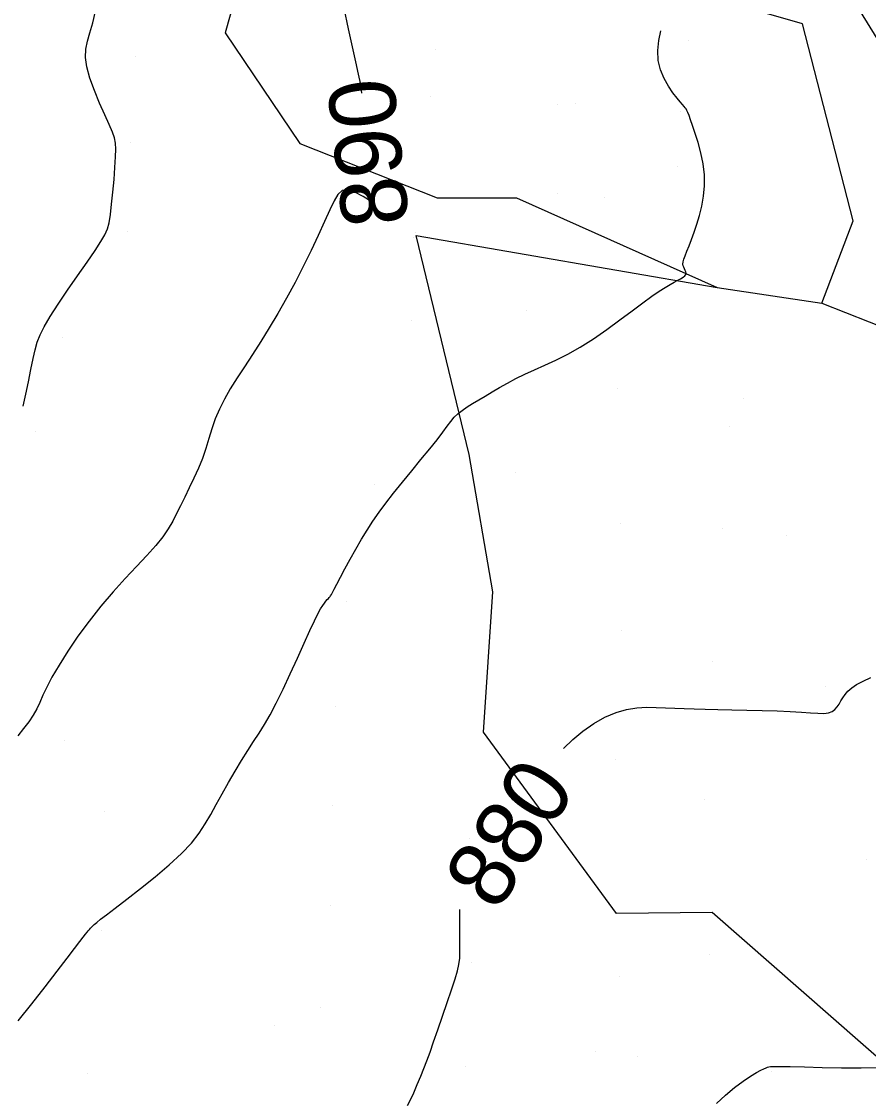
# Model space of a CAD drawing. Extents: x 400243 to 403697, y 4403637 to 4408083.
# Drawn here: x 402712.4 to 402808, y 4406336.6 to 4406458.2 of the extents above; entities that cross this region are included whole.
import ezdxf

# ---------------------------------------------------------------- set-up
doc = ezdxf.new("R2010")
doc.units = 0
doc.layers.add('HH_IC', color=7, linetype='Continuous')

msp = doc.modelspace()

# ---------------------------------------------------------------- linework, layer by layer
at = {"layer": 'HH_IC'}
for p, q in [((402811.77, 4406451.75), (402794.37, 4406479.94)), ((402741.45, 4406477.95), (402735.33, 4406456.95)), ((402800.55, 4406457.97), (402787.42, 4406461.72)), ((402800.55, 4406457.97), (402800.55, 4406457.97)), ((402806.25, 4406435.71), (402800.55, 4406457.97)), ((402800.55, 4406457.97), (402800.55, 4406457.97)), ((402735.33, 4406456.95), (402735.33, 4406456.95)), ((402735.33, 4406456.95), (402743.78, 4406444.44)), ((402787.68, 4406456.03), (402787.68, 4406456.03)), ((402759.14, 4406455.04), (402759.14, 4406455.04)), ((402725.25, 4406454.24), (402725.25, 4406454.24)), ((402758.53, 4406449.7), (402758.53, 4406449.7)), ((402772.89, 4406448.85), (402772.89, 4406448.85)), ((402774.87, 4406448.92), (402774.87, 4406448.92)), ((402786.8, 4406448.02), (402786.8, 4406448.02)), ((402724.71, 4406444.5), (402724.71, 4406444.5)), ((402743.78, 4406444.44), (402743.78, 4406444.44)), ((402743.78, 4406444.44), (402759.27, 4406438.32)), ((402786.39, 4406441.9), (402786.39, 4406441.9)), ((402772.89, 4406438.75), (402772.89, 4406438.75)), ((402759.27, 4406438.32), (402759.27, 4406438.32)), ((402759.27, 4406438.32), (402768.24, 4406438.3)), ((402768.24, 4406438.3), (402768.24, 4406438.3)), ((402768.24, 4406438.3), (402790.92, 4406428.17)), ((402778.14, 4406438.39), (402778.14, 4406438.39)), ((402802.71, 4406426.43), (402806.25, 4406435.71)), ((402806.25, 4406435.71), (402806.25, 4406435.71)), ((402724.3, 4406434.45), (402724.3, 4406434.45)), ((402756.82, 4406434.41), (402756.82, 4406434.41)), ((402756.92, 4406434.05), (402756.92, 4406434.05)), ((402762.89, 4406409.32), (402756.92, 4406434.05)), ((402756.92, 4406434.05), (402790.92, 4406428.17)), ((402756.61, 4406433.86), (402756.61, 4406433.86)), ((402790.92, 4406428.17), (402790.92, 4406428.17)), ((402790.92, 4406428.17), (402802.71, 4406426.43)), ((402769.41, 4406425.58), (402769.41, 4406425.58)), ((402802.71, 4406426.43), (402802.71, 4406426.43)), ((402802.71, 4406426.43), (402821.63, 4406418.88)), ((402756.36, 4406424.44), (402756.36, 4406424.44)), ((402716.99, 4406422.51), (402716.99, 4406422.51)), ((402779.69, 4406416.79), (402779.69, 4406416.79)), ((402793.84, 4406415.68), (402793.84, 4406415.68)), ((402713.98, 4406411.98), (402713.98, 4406411.98)), ((402792.27, 4406412.53), (402792.27, 4406412.53)), ((402765.58, 4406393.82), (402762.89, 4406409.32)), ((402768.08, 4406407.31), (402768.08, 4406407.31)), ((402752.2, 4406405.92), (402752.2, 4406405.92)), ((402780.01, 4406401.55), (402780.01, 4406401.55)), ((402791.56, 4406400.96), (402791.56, 4406400.96)), ((402798.75, 4406400.15), (402798.75, 4406400.15)), ((402764.52, 4406377.97), (402765.58, 4406393.82)), ((402765.58, 4406393.82), (402765.58, 4406393.82)), ((402749.03, 4406392.75), (402749.03, 4406392.75)), ((402765.32, 4406391.24), (402765.32, 4406391.24)), ((402780.09, 4406389.48), (402780.09, 4406389.48)), ((402790.4, 4406385.9), (402790.4, 4406385.9)), ((402803.14, 4406383.11), (402803.14, 4406383.11)), ((402747.83, 4406380.9), (402747.83, 4406380.9)), ((402764.52, 4406377.97), (402764.52, 4406377.97)), ((402779.54, 4406357.52), (402764.52, 4406377.97)), ((402717.25, 4406376.99), (402717.25, 4406376.99)), ((402779.38, 4406374.92), (402779.38, 4406374.92)), ((402747.52, 4406369.72), (402747.52, 4406369.72)), ((402789.48, 4406370.4), (402789.48, 4406370.4)), ((402721.69, 4406369.07), (402721.69, 4406369.07)), ((402762.91, 4406365.92), (402762.91, 4406365.92)), ((402807.78, 4406363.58), (402807.78, 4406363.58)), ((402747.23, 4406358.37), (402747.23, 4406358.37)), ((402790.33, 4406357.62), (402779.54, 4406357.52)), ((402779.54, 4406357.52), (402779.54, 4406357.52)), ((402790.33, 4406357.62), (402790.33, 4406357.62)), ((402817.62, 4406333.67), (402790.33, 4406357.62)), ((402721.33, 4406355.62), (402721.33, 4406355.62)), ((402790.07, 4406352.89), (402790.07, 4406352.89)), ((402763.19, 4406351.96), (402763.19, 4406351.96)), ((402779.89, 4406350.38), (402779.89, 4406350.38)), ((402746.12, 4406346.89), (402746.12, 4406346.89)), ((402740.92, 4406344.82), (402740.92, 4406344.82)), ((402777.18, 4406341.93), (402777.18, 4406341.93)), ((402762.5, 4406340.27), (402762.5, 4406340.27)), ((402781.86, 4406341.41), (402781.86, 4406341.41)), ((402719.84, 4406339.43), (402719.84, 4406339.43)), ((402797.09, 4406339.64), (402797.09, 4406339.64))]:
    msp.add_line(p, q, dxfattribs=at)
for points in [[(402748.74, 4406459.74), (402749.23, 4406457.38), (402749.68, 4406455.37), (402750.06, 4406453.68), (402750.38, 4406452.28), (402750.61, 4406451.11), (402750.75, 4406450.13)], [(402712.55, 4406414.79), (402712.85, 4406416.14), (402713.14, 4406417.55), (402713.41, 4406418.93), (402713.66, 4406420.15), (402713.88, 4406421.15), (402714.12, 4406422.01), (402714.44, 4406422.84), (402714.91, 4406423.76), (402715.58, 4406424.89), (402716.49, 4406426.29), (402717.56, 4406427.88), (402718.68, 4406429.51), (402719.75, 4406431.05), (402720.66, 4406432.37), (402721.32, 4406433.36), (402721.77, 4406434.12), (402722.06, 4406434.79), (402722.25, 4406435.5), (402722.39, 4406436.41), (402722.53, 4406437.59), (402722.67, 4406438.96), (402722.8, 4406440.39), (402722.9, 4406441.75), (402722.98, 4406442.92), (402723.01, 4406443.79), (402722.98, 4406444.47), (402722.86, 4406445.07), (402722.62, 4406445.73), (402722.26, 4406446.57), (402721.75, 4406447.69), (402721.16, 4406449.01), (402720.58, 4406450.43), (402720.07, 4406451.83), (402719.71, 4406453.1), (402719.57, 4406454.16), (402719.62, 4406455.09), (402719.8, 4406455.98), (402720.08, 4406456.93), (402720.4, 4406458.05), (402720.72, 4406459.4)], [(402711.96, 4406345.37), (402713.52, 4406347.32), (402715.02, 4406349.23), (402716.37, 4406350.99), (402717.49, 4406352.46), (402718.33, 4406353.56), (402718.93, 4406354.33), (402719.32, 4406354.85), (402719.58, 4406355.17), (402719.75, 4406355.39), (402719.89, 4406355.56), (402720.02, 4406355.71), (402720.13, 4406355.84), (402720.25, 4406355.96), (402720.39, 4406356.1), (402720.57, 4406356.26), (402720.84, 4406356.49), (402721.28, 4406356.85), (402721.95, 4406357.37), (402722.93, 4406358.12), (402724.24, 4406359.13), (402725.79, 4406360.33), (402727.43, 4406361.64), (402729.02, 4406362.99), (402730.43, 4406364.28), (402731.54, 4406365.46), (402732.4, 4406366.56), (402733.1, 4406367.62), (402733.71, 4406368.69), (402734.32, 4406369.81), (402735, 4406371.03), (402735.72, 4406372.29), (402736.47, 4406373.56), (402737.21, 4406374.79), (402737.91, 4406375.92), (402738.56, 4406376.92), (402739.18, 4406377.86), (402739.79, 4406378.84), (402740.43, 4406379.94), (402741.12, 4406381.25), (402741.89, 4406382.83), (402742.7, 4406384.57), (402743.5, 4406386.35), (402744.25, 4406388.02), (402744.9, 4406389.46), (402745.42, 4406390.56), (402745.82, 4406391.35), (402746.13, 4406391.91), (402746.36, 4406392.28), (402746.56, 4406392.55), (402746.72, 4406392.76), (402746.87, 4406392.94), (402747, 4406393.08), (402747.1, 4406393.19), (402747.19, 4406393.29), (402747.26, 4406393.38), (402747.34, 4406393.52), (402747.46, 4406393.74), (402747.65, 4406394.11), (402747.95, 4406394.67), (402748.36, 4406395.46), (402748.87, 4406396.43), (402749.46, 4406397.51), (402750.09, 4406398.64), (402750.74, 4406399.75), (402751.38, 4406400.8), (402752.03, 4406401.8), (402752.73, 4406402.8), (402753.5, 4406403.84), (402754.37, 4406404.96), (402755.36, 4406406.19), (402756.41, 4406407.48), (402757.46, 4406408.75), (402758.44, 4406409.95), (402759.27, 4406411), (402759.92, 4406411.85), (402760.42, 4406412.53), (402760.83, 4406413.07), (402761.2, 4406413.53), (402761.61, 4406413.93), (402762.09, 4406414.31), (402762.66, 4406414.7), (402763.29, 4406415.09), (402763.98, 4406415.49), (402764.72, 4406415.93), (402765.51, 4406416.39), (402766.34, 4406416.88), (402767.23, 4406417.38), (402768.18, 4406417.89), (402769.2, 4406418.39), (402770.29, 4406418.89), (402771.46, 4406419.4), (402772.7, 4406419.97), (402774.03, 4406420.64), (402775.44, 4406421.44), (402776.93, 4406422.4), (402778.44, 4406423.45), (402779.92, 4406424.52), (402781.3, 4406425.55), (402782.52, 4406426.46), (402783.53, 4406427.19), (402784.36, 4406427.76), (402785.04, 4406428.2), (402785.59, 4406428.53), (402786.05, 4406428.79), (402786.45, 4406429), (402786.78, 4406429.18), (402787.05, 4406429.34), (402787.24, 4406429.49), (402787.36, 4406429.64), (402787.39, 4406429.79), (402787.36, 4406429.95), (402787.29, 4406430.12), (402787.2, 4406430.29), (402787.12, 4406430.46), (402787.06, 4406430.63), (402787.04, 4406430.83), (402787.07, 4406431.07), (402787.15, 4406431.37), (402787.28, 4406431.77), (402787.48, 4406432.28), (402787.73, 4406432.9), (402788.01, 4406433.61), (402788.32, 4406434.43), (402788.62, 4406435.33), (402788.92, 4406436.32), (402789.18, 4406437.38), (402789.37, 4406438.5), (402789.48, 4406439.68), (402789.46, 4406440.9), (402789.31, 4406442.15), (402789.06, 4406443.38), (402788.75, 4406444.54), (402788.42, 4406445.58), (402788.13, 4406446.46), (402787.9, 4406447.12), (402787.73, 4406447.61), (402787.6, 4406447.95), (402787.49, 4406448.18), (402787.4, 4406448.35), (402787.3, 4406448.48), (402787.17, 4406448.63), (402786.99, 4406448.83), (402786.73, 4406449.13), (402786.38, 4406449.56), (402785.91, 4406450.16), (402785.4, 4406450.9), (402784.9, 4406451.78), (402784.49, 4406452.76), (402784.25, 4406453.82), (402784.21, 4406454.93), (402784.33, 4406456.06), (402784.54, 4406457.17)], [(402752.12, 4406437.71), (402750.93, 4406438.45), (402749.91, 4406438.99), (402749.12, 4406439.21), (402748.54, 4406439.12), (402748.07, 4406438.7), (402747.64, 4406437.98), (402747.15, 4406436.94), (402746.55, 4406435.62), (402745.84, 4406434.06), (402745.04, 4406432.35), (402744.16, 4406430.55), (402743.24, 4406428.73), (402742.28, 4406426.96), (402741.3, 4406425.25), (402740.32, 4406423.62), (402739.36, 4406422.07), (402738.42, 4406420.61), (402737.53, 4406419.24), (402736.7, 4406417.97), (402735.93, 4406416.75), (402735.26, 4406415.59), (402734.69, 4406414.45), (402734.22, 4406413.34), (402733.84, 4406412.23), (402733.49, 4406411.12), (402733.15, 4406410.01), (402732.77, 4406408.89), (402732.32, 4406407.77), (402731.82, 4406406.65), (402731.3, 4406405.56), (402730.78, 4406404.51), (402730.3, 4406403.54), (402729.86, 4406402.65), (402729.42, 4406401.79), (402728.92, 4406400.94), (402728.31, 4406400.04), (402727.52, 4406399.05), (402726.52, 4406397.93), (402725.35, 4406396.68), (402724.05, 4406395.31), (402722.69, 4406393.82), (402721.31, 4406392.21), (402719.98, 4406390.52), (402718.72, 4406388.8), (402717.58, 4406387.12), (402716.59, 4406385.56), (402715.79, 4406384.19), (402715.2, 4406383.06), (402714.77, 4406382.14), (402714.42, 4406381.34), (402714.08, 4406380.63), (402713.67, 4406379.91), (402713.16, 4406379.16), (402712.56, 4406378.38), (402711.92, 4406377.58)], [(402773.54, 4406376.14), (402774.6, 4406377.15), (402775.75, 4406378.1), (402776.98, 4406378.95), (402778.23, 4406379.66), (402779.48, 4406380.2), (402780.67, 4406380.55), (402781.83, 4406380.74), (402782.95, 4406380.8), (402784.03, 4406380.78), (402785.08, 4406380.73), (402786.11, 4406380.68), (402787.17, 4406380.64), (402788.3, 4406380.6), (402789.55, 4406380.57), (402790.96, 4406380.54), (402792.55, 4406380.51), (402794.26, 4406380.47), (402796, 4406380.44), (402797.66, 4406380.39), (402799.16, 4406380.32), (402800.42, 4406380.24), (402801.45, 4406380.16), (402802.28, 4406380.11), (402802.95, 4406380.1), (402803.47, 4406380.17), (402803.88, 4406380.31), (402804.2, 4406380.54), (402804.46, 4406380.82), (402804.68, 4406381.14), (402804.88, 4406381.5), (402805.09, 4406381.87), (402805.35, 4406382.24), (402805.67, 4406382.62), (402806.09, 4406383), (402806.65, 4406383.37), (402807.38, 4406383.74), (402808.27, 4406384.15)], [(402755.95, 4406335.83), (402756.56, 4406337.07), (402757.04, 4406338.18), (402757.44, 4406339.13), (402757.79, 4406340), (402758.12, 4406340.88), (402758.48, 4406341.85), (402758.89, 4406343), (402759.37, 4406344.38), (402759.9, 4406345.9), (402760.43, 4406347.45), (402760.91, 4406348.89), (402761.3, 4406350.11), (402761.58, 4406351.02), (402761.74, 4406351.75), (402761.83, 4406352.46), (402761.86, 4406353.32), (402761.86, 4406354.49), (402761.85, 4406356.08), (402761.84, 4406357.95)], [(402790.82, 4406336.06), (402791.83, 4406337), (402792.86, 4406337.84), (402793.83, 4406338.56), (402794.67, 4406339.13), (402795.34, 4406339.54), (402795.83, 4406339.81), (402796.19, 4406339.98), (402796.43, 4406340.08), (402796.6, 4406340.14), (402796.72, 4406340.19), (402796.92, 4406340.22), (402797.31, 4406340.24), (402798, 4406340.24), (402799.13, 4406340.22), (402800.75, 4406340.18), (402802.75, 4406340.12), (402804.95, 4406340.08), (402807.17, 4406340.06), (402809.23, 4406340.1)]]:
    msp.add_lwpolyline(points, dxfattribs=at)

# ---------------------------------------------------------------- texts
for s, rotation, p in [('890', 96.3142, (402756.14, 4406435.48)), ('880', 57.2486, (402766.03, 4406357.53))]:
    msp.add_text(s, height=7.5, rotation=rotation, dxfattribs=at).set_placement(p)

doc.saveas('drawing.dxf')
